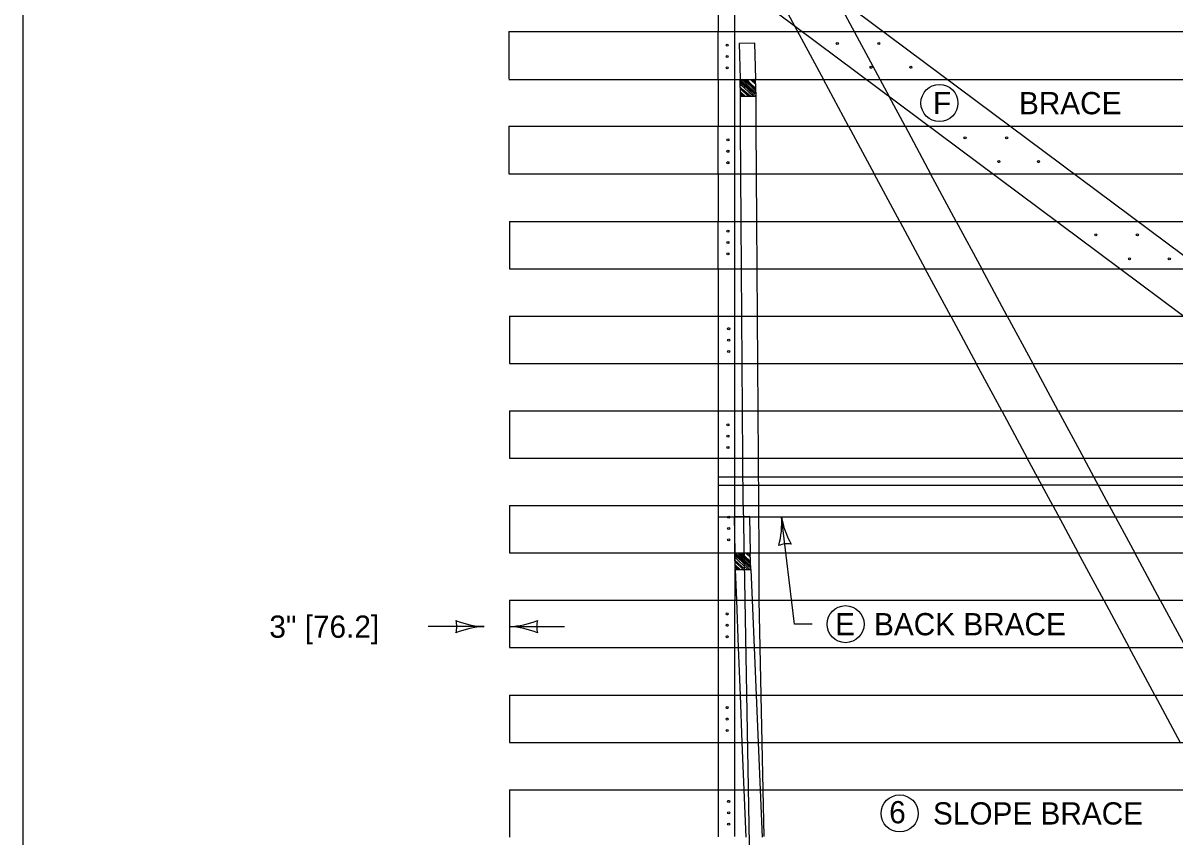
# Model space of a CAD drawing. Extents: x 49991.4 to 50021, y 49987.6 to 50011.4.
# Drawn here: x 49999.384 to 50002.489, y 49994.927 to 49997.122 of the extents above; entities that cross this region are included whole.
import ezdxf

# ---------------------------------------------------------------- set-up
doc = ezdxf.new("R2010")
doc.units = 0
for name, color, linetype in [('Level 1', 7, 'Continuous'), ('Level 2', 7, 'Continuous'), ('Level 3', 7, 'Continuous'), ('Level 4', 7, 'Continuous')]:
    doc.layers.add(name, color=color, linetype=linetype)

msp = doc.modelspace()

# ---------------------------------------------------------------- linework, layer by layer
at = {"layer": 'Level 1'}
for p, q in [((50004.8448, 49994.752), (50001.0146, 49997.6127)), ((50004.7604, 49994.652), (50000.9301, 49997.5128)), ((50001.2572, 49997.2268), (50001.2572, 49997.099)), ((50001.3024, 49997.099), (50001.3024, 49997.2268)), ((50000.6929, 49997.099), (50000.6929, 49996.9713)), ((50000.6929, 49997.099), (50001.4842, 49997.099)), ((50001.7026, 49997.099), (50005.041, 49997.099)), ((50000.6929, 49996.97), (50001.6568, 49996.97)), ((50001.2572, 49996.97), (50001.2572, 49996.8435)), ((50001.3024, 49996.8435), (50001.3024, 49996.97)), ((50001.3176, 49996.9244), (50001.3167, 49996.97)), ((50001.3598, 49996.9244), (50001.3582, 49996.9713)), ((50001.6092, 49996.8435), (50001.5412, 49996.97)), ((50001.8753, 49996.97), (50005.041, 49996.97)), ((50001.3176, 49996.9244), (50001.3598, 49996.9244)), ((50001.3182, 49996.8435), (50001.3176, 49996.9244)), ((50001.3603, 49996.8435), (50001.3598, 49996.9244)), ((50001.7616, 49996.8435), (50001.7182, 49996.9241)), ((50000.6929, 49996.8435), (50000.6929, 49996.7157)), ((50000.6929, 49996.8435), (50001.8262, 49996.8435)), ((50002.0446, 49996.8435), (50005.041, 49996.8435)), ((50000.6929, 49996.7157), (50001.9973, 49996.7157)), ((50001.2572, 49996.7157), (50001.2572, 49996.587)), ((50001.3024, 49996.587), (50001.3024, 49996.7157)), ((50001.3198, 49996.587), (50001.3189, 49996.7157)), ((50001.362, 49996.587), (50001.3611, 49996.7157)), ((50001.7473, 49996.587), (50001.678, 49996.7157)), ((50001.8995, 49996.587), (50001.8304, 49996.7157)), ((50002.2158, 49996.7157), (50005.041, 49996.7157)), ((50000.6947, 49996.587), (50000.6947, 49996.4592)), ((50000.6947, 49996.587), (50001.8995, 49996.587)), ((50001.8995, 49996.587), (50002.1695, 49996.587)), ((50002.3879, 49996.587), (50005.0428, 49996.587)), ((50000.6947, 49996.4592), (50002.3406, 49996.4592)), ((50001.2572, 49996.4592), (50001.2572, 49996.3316)), ((50001.3024, 49996.3316), (50001.3024, 49996.4592)), ((50001.3215, 49996.3316), (50001.3208, 49996.4592)), ((50001.3635, 49996.3316), (50001.3628, 49996.4592)), ((50001.8847, 49996.3316), (50001.8159, 49996.4592)), ((50002.0371, 49996.3316), (50001.9683, 49996.4592)), ((50000.6947, 49996.3316), (50000.6947, 49996.2038)), ((50000.6947, 49996.3316), (50002.5117, 49996.3316)), ((50000.6947, 49996.2038), (50002.6826, 49996.2038)), ((50001.2572, 49996.2038), (50001.2572, 49996.076)), ((50001.3024, 49996.076), (50001.3024, 49996.2038)), ((50001.3232, 49996.076), (50001.3223, 49996.2038)), ((50001.3652, 49996.076), (50001.3643, 49996.2038)), ((50002.0221, 49996.076), (50001.9533, 49996.2038)), ((50002.1745, 49996.076), (50002.1057, 49996.2038)), ((50000.6947, 49996.076), (50000.6947, 49995.9482)), ((50000.6947, 49996.076), (50002.8537, 49996.076)), ((50000.6947, 49995.9482), (50003.0248, 49995.9482)), ((50001.2572, 49995.9482), (50001.2572, 49995.8204)), ((50001.3024, 49995.8204), (50001.3024, 49995.9482)), ((50001.3249, 49995.8204), (50001.324, 49995.9482)), ((50001.3669, 49995.8204), (50001.366, 49995.9482)), ((50002.1595, 49995.8204), (50002.0909, 49995.9482)), ((50002.3119, 49995.8204), (50002.2432, 49995.9482)), ((50001.3024, 49995.898), (50001.3244, 49995.898)), ((50001.3024, 49995.8757), (50001.3245, 49995.8757)), ((50001.3664, 49995.898), (50002.1178, 49995.898)), ((50001.3665, 49995.8757), (50002.1298, 49995.8757)), ((50002.2702, 49995.898), (50002.8073, 49995.898)), ((50002.2822, 49995.8757), (50002.8072, 49995.8757)), ((50000.6947, 49995.8204), (50000.6947, 49995.6928)), ((50000.6947, 49995.8204), (50003.1959, 49995.8204)), ((50000.6947, 49995.6928), (50003.367, 49995.6928)), ((50001.2572, 49995.6936), (50001.2572, 49995.565)), ((50001.3033, 49995.6483), (50001.3024, 49995.6939)), ((50001.3024, 49995.6927), (50001.3024, 49995.565)), ((50001.3455, 49995.6483), (50001.3441, 49995.693)), ((50001.3685, 49995.565), (50001.3677, 49995.6928)), ((50002.2971, 49995.565), (50002.2283, 49995.6928)), ((50002.4493, 49995.565), (50002.3806, 49995.6928)), ((50001.3033, 49995.6483), (50001.3455, 49995.6483)), ((50001.3033, 49995.6483), (50001.3067, 49995.565)), ((50001.3455, 49995.6483), (50001.349, 49995.565)), ((50000.6947, 49995.565), (50000.6947, 49995.4372)), ((50000.6947, 49995.565), (50003.5379, 49995.565)), ((50000.6947, 49995.4372), (50003.709, 49995.4372)), ((50001.2572, 49995.4372), (50001.2572, 49995.3094)), ((50001.3024, 49995.3094), (50001.3024, 49995.4372)), ((50001.3118, 49995.4372), (50001.3167, 49995.3094)), ((50001.3543, 49995.4372), (50001.3596, 49995.3094)), ((50001.3735, 49995.3094), (50001.3711, 49995.4372)), ((50002.4345, 49995.3094), (50002.3657, 49995.4372)), ((50000.6947, 49995.3094), (50003.8801, 49995.3094)), ((50000.6947, 49995.3094), (50000.6947, 49995.1816)), ((50000.6947, 49995.1816), (50004.0512, 49995.1816)), ((50001.2572, 49995.1816), (50001.2572, 49995.054)), ((50001.3024, 49995.054), (50001.3024, 49995.1816)), ((50001.3218, 49995.1816), (50001.3269, 49995.054)), ((50001.3651, 49995.1816), (50001.3704, 49995.054)), ((50001.3787, 49995.054), (50001.3763, 49995.1816)), ((50000.6947, 49995.054), (50000.6947, 49994.9262)), ((50000.6947, 49995.054), (50004.2222, 49995.054))]:
    msp.add_line(p, q, dxfattribs=at)
msp.add_lwpolyline([(49999.3835, 49998.9992), (50016.7501, 49998.9992), (50016.7501, 49987.7988), (49999.3835, 49987.7988)], close=True, dxfattribs=at)
for points in [[(50001.3167, 49996.9657), (50001.317, 49996.9655), (50001.3293, 49996.9553), (50001.3416, 49996.9443), (50001.3568, 49996.9302)], [(50001.3597, 49996.93), (50001.3429, 49996.9454), (50001.3306, 49996.9565), (50001.3205, 49996.9662), (50001.3171, 49996.9699)], [(50001.3594, 49996.9327), (50001.3516, 49996.9401), (50001.3406, 49996.9509), (50001.3265, 49996.9653), (50001.3216, 49996.9699)], [(50001.3594, 49996.9379), (50001.3453, 49996.9516), (50001.3269, 49996.9692), (50001.3263, 49996.9698)], [(50001.3594, 49996.9408), (50001.3513, 49996.9492), (50001.3298, 49996.97)], [(50001.3592, 49996.9453), (50001.3522, 49996.9521), (50001.34, 49996.9633), (50001.3333, 49996.97)], [(50001.3588, 49996.9565), (50001.3576, 49996.9577), (50001.3481, 49996.966), (50001.3444, 49996.9699)], [(50001.3585, 49996.9607), (50001.3577, 49996.9614), (50001.3483, 49996.9701)], [(50001.3584, 49996.9637), (50001.3533, 49996.9685), (50001.352, 49996.97)], [(50001.354, 49996.9276), (50001.3366, 49996.9447), (50001.3279, 49996.9531), (50001.3226, 49996.9566), (50001.3188, 49996.9588), (50001.3169, 49996.9607)], [(50001.354, 49996.9276), (50001.3366, 49996.9447), (50001.3279, 49996.9531), (50001.3226, 49996.9566), (50001.3188, 49996.9588), (50001.3169, 49996.9607)], [(50001.352, 49996.9246), (50001.3287, 49996.9461), (50001.3223, 49996.9517), (50001.317, 49996.9557)], [(50001.3443, 49996.9244), (50001.3244, 49996.9422), (50001.3171, 49996.9492)], [(50001.339, 49996.9244), (50001.3172, 49996.9444), (50001.3172, 49996.9444)], [(50001.3308, 49996.9244), (50001.3186, 49996.9357), (50001.3174, 49996.937)], [(50001.3278, 49996.9244), (50001.3228, 49996.9288), (50001.3174, 49996.9338)], [(50001.3235, 49996.9244), (50001.3228, 49996.925), (50001.3175, 49996.9297)], [(50001.3578, 49996.9244), (50001.3557, 49996.9262)], [(50001.3583, 49996.9288), (50001.3596, 49996.9276)], [(50001.3453, 49995.6518), (50001.3274, 49995.6682), (50001.3152, 49995.6792), (50001.3028, 49995.6894), (50001.3026, 49995.6896)], [(50001.3454, 49995.6539), (50001.3287, 49995.6695), (50001.3165, 49995.6804), (50001.3063, 49995.6902), (50001.3037, 49995.6928)], [(50001.3452, 49995.6566), (50001.3374, 49995.664), (50001.3265, 49995.6748), (50001.3123, 49995.6893), (50001.3084, 49995.6929)], [(50001.345, 49995.662), (50001.3312, 49995.6755), (50001.3128, 49995.693)], [(50001.3451, 49995.6649), (50001.3371, 49995.6733), (50001.3163, 49995.6931)], [(50001.3449, 49995.6693), (50001.3379, 49995.676), (50001.3258, 49995.6872), (50001.3204, 49995.6925)], [(50001.3444, 49995.6806), (50001.3434, 49995.6816), (50001.3339, 49995.6899), (50001.3311, 49995.6928)], [(50001.3444, 49995.6845), (50001.3434, 49995.6854), (50001.3354, 49995.6928)], [(50001.3443, 49995.6875), (50001.3391, 49995.6924), (50001.3386, 49995.693)], [(50001.3432, 49995.6484), (50001.3223, 49995.6686), (50001.3137, 49995.677), (50001.3084, 49995.6806), (50001.3046, 49995.6828), (50001.3027, 49995.6846)], [(50001.3378, 49995.6484), (50001.3145, 49995.67), (50001.308, 49995.6756), (50001.3028, 49995.6796)], [(50001.33, 49995.6483), (50001.3102, 49995.6661), (50001.3028, 49995.6731)], [(50001.3247, 49995.6483), (50001.3031, 49995.6683), (50001.3031, 49995.6683)], [(50001.3166, 49995.6483), (50001.3044, 49995.6596), (50001.3031, 49995.6609)], [(50001.3136, 49995.6483), (50001.3087, 49995.6527), (50001.3032, 49995.6578)], [(50001.3093, 49995.6483), (50001.3085, 49995.649), (50001.3033, 49995.6536)]]:
    msp.add_lwpolyline(points, dxfattribs=at)
for centre in [(50001.2819, 49997.0623), (50001.5787, 49997.0672), (50001.6909, 49997.0672), (50001.2819, 49997.0316), (50001.2819, 49997.001), (50001.6698, 49997.0027), (50001.7769, 49997.0027), (50001.2839, 49996.8068), (50001.9231, 49996.8127), (50002.0353, 49996.8127), (50001.2839, 49996.7761), (50001.2839, 49996.7454), (50002.0143, 49996.7482), (50002.1213, 49996.7482), (50001.2839, 49996.5606), (50001.2839, 49996.5299), (50002.2756, 49996.5507), (50002.3878, 49996.5507), (50001.2839, 49996.4992), (50002.3667, 49996.4862), (50002.4738, 49996.4862), (50001.2859, 49996.2976), (50001.2859, 49996.2669), (50001.2859, 49996.2362), (50001.2839, 49996.0383), (50001.2839, 49996.0076), (50001.2839, 49995.977), (50001.2859, 49995.7892), (50001.2859, 49995.7586), (50001.2859, 49995.7279), (50001.2819, 49995.5281), (50001.2819, 49995.4975), (50001.2819, 49995.4668), (50001.2819, 49995.2754), (50001.2819, 49995.2447), (50001.2819, 49995.2141), (50001.2859, 49995.0226), (50001.2859, 49994.992), (50001.2859, 49994.9613)]:
    msp.add_ellipse(centre, major_axis=(0.00285, 0), ratio=0.940299, dxfattribs=at)
at = {"layer": 'Level 2'}
for centre in [(50001.8541, 49996.9064), (50001.601, 49995.5006), (50001.7468, 49994.9901)]:
    msp.add_circle(centre, 0.05, dxfattribs=at)
at = {"layer": 'Level 3'}
for p, q in [((50001.4635, 49995.5006), (50001.4283, 49995.7899)), ((50000.6266, 49995.4939), (50000.4761, 49995.4939)), ((50000.6947, 49995.4939), (50000.8437, 49995.4939)), ((50001.511, 49995.5006), (50001.4635, 49995.5006))]:
    msp.add_line(p, q, dxfattribs=at)
for centre, radius, start, end in [((50001.2067, 49995.7722), 0.2223, 344.389, 4.5726), ((50001.6579, 49995.8294), 0.233, 189.7603, 209.0102), ((50001.4438, 49995.6626), 0.0548, 79.0719, 114.7942), ((50000.6358, 49995.716), 0.2223, 247.456, 267.6395), ((50000.4984, 49995.4939), 0.0548, 342.1388, 17.8612), ((50000.6832, 49995.7266), 0.233, 272.8273, 292.0772), ((50000.8229, 49995.4939), 0.0548, 162.1388, 197.8612), ((50000.6381, 49995.2612), 0.233, 92.8273, 112.0772), ((50000.6855, 49995.2718), 0.2223, 67.456, 87.6395)]:
    msp.add_arc(centre, radius, start, end, dxfattribs=at)
at = {"layer": 'Level 4'}
for p, q in [((50001.3169, 49997.3871), (50001.5412, 49996.97)), ((50001.5715, 49997.1969), (50001.7182, 49996.9241)), ((50001.2572, 49996.97), (50001.2572, 49997.099)), ((50001.3024, 49996.97), (50001.3024, 49997.099)), ((50001.4842, 49997.099), (50001.7026, 49997.099)), ((50001.3566, 49997.0674), (50001.3146, 49997.0666)), ((50001.3146, 49997.0666), (50001.3166, 49996.9713)), ((50001.3587, 49996.9713), (50001.3566, 49997.0674)), ((50001.6568, 49996.97), (50001.8753, 49996.97)), ((50001.2572, 49996.7157), (50001.2572, 49996.8435)), ((50001.3024, 49996.7157), (50001.3024, 49996.8435)), ((50001.3189, 49996.7157), (50001.3182, 49996.8435)), ((50001.3611, 49996.7157), (50001.3603, 49996.8435)), ((50001.6092, 49996.8435), (50001.678, 49996.7157)), ((50001.7616, 49996.8435), (50001.8304, 49996.7157)), ((50001.8262, 49996.8435), (50002.0446, 49996.8435)), ((50001.9973, 49996.7157), (50002.2158, 49996.7157)), ((50001.2572, 49996.4592), (50001.2572, 49996.587)), ((50001.3024, 49996.4592), (50001.3024, 49996.587)), ((50001.3208, 49996.4592), (50001.3198, 49996.587)), ((50001.3628, 49996.4592), (50001.362, 49996.587)), ((50001.7473, 49996.587), (50001.8159, 49996.4592)), ((50001.8995, 49996.587), (50001.9683, 49996.4592)), ((50002.1695, 49996.587), (50002.3879, 49996.587)), ((50002.3406, 49996.4592), (50002.559, 49996.4592)), ((50001.2572, 49996.3316), (50001.2572, 49996.2038)), ((50001.3024, 49996.2038), (50001.3024, 49996.3316)), ((50001.3223, 49996.2038), (50001.3215, 49996.3316)), ((50001.3644, 49996.2038), (50001.3635, 49996.3316)), ((50001.8847, 49996.3316), (50001.9533, 49996.2038)), ((50002.0371, 49996.3316), (50002.1057, 49996.2038)), ((50001.2572, 49996.0751), (50001.2572, 49995.9482)), ((50001.3024, 49995.9482), (50001.3024, 49996.076)), ((50001.324, 49995.9482), (50001.3232, 49996.076)), ((50001.3661, 49995.9482), (50001.3652, 49996.076)), ((50002.0221, 49996.076), (50002.0909, 49995.9482)), ((50002.1745, 49996.076), (50002.2432, 49995.9482)), ((50001.2572, 49995.898), (50001.3024, 49995.898)), ((50001.2572, 49995.8757), (50001.3024, 49995.8757)), ((50001.3244, 49995.898), (50001.3664, 49995.898)), ((50001.3245, 49995.8757), (50001.3665, 49995.8757)), ((50002.1178, 49995.898), (50002.2702, 49995.898)), ((50002.2822, 49995.8757), (50002.1298, 49995.8757)), ((50001.2572, 49995.8194), (50001.2572, 49995.6936)), ((50001.3024, 49995.693), (50001.3024, 49995.8187)), ((50001.3249, 49995.8204), (50001.3455, 49994.6706)), ((50001.3677, 49995.6928), (50001.3669, 49995.8204)), ((50002.1595, 49995.8204), (50002.2283, 49995.6928)), ((50002.3119, 49995.8204), (50002.3806, 49995.6928)), ((50001.2572, 49995.7899), (50004.4313, 49995.7899)), ((50001.3425, 49995.7913), (50001.3005, 49995.7905)), ((50001.3005, 49995.7905), (50001.3024, 49995.6952)), ((50001.3446, 49995.6932), (50001.3425, 49995.7913)), ((50001.2572, 49995.565), (50001.2572, 49995.4393)), ((50001.3024, 49995.4382), (50001.3024, 49995.565)), ((50001.3067, 49995.565), (50001.3118, 49995.4372)), ((50001.349, 49995.565), (50001.3543, 49995.4372)), ((50001.3711, 49995.4382), (50001.3685, 49995.565)), ((50002.2971, 49995.565), (50002.3657, 49995.4372)), ((50002.4493, 49995.565), (50002.5181, 49995.4372)), ((50001.2572, 49995.3085), (50001.2572, 49995.1816)), ((50001.3024, 49995.1816), (50001.3024, 49995.3074)), ((50001.3167, 49995.3094), (50001.3218, 49995.1816)), ((50001.3596, 49995.3094), (50001.3651, 49995.1816)), ((50001.376, 49995.1816), (50001.3735, 49995.3085)), ((50002.4345, 49995.3094), (50002.5032, 49995.1816)), ((50001.2572, 49995.054), (50001.2572, 49994.9269)), ((50001.3024, 49994.9276), (50001.3024, 49995.054)), ((50001.3269, 49995.054), (50001.3318, 49994.9262)), ((50001.3704, 49995.054), (50001.3758, 49994.9262)), ((50001.3812, 49994.9276), (50001.3787, 49995.054))]:
    msp.add_line(p, q, dxfattribs=at)

# ---------------------------------------------------------------- texts
at = {"layer": 'Level 2'}
for s, p in [('F', (50001.8369, 49996.8765)), ('BRACE', (50002.0685, 49996.876)), ('3" [76.2]', (50000.0475, 49995.4639)), ('E', (50001.573, 49995.4706)), ('BACK BRACE', (50001.6778, 49995.4706)), ('6', (50001.7187, 49994.9634)), ('SLOPE BRACE', (50001.8368, 49994.9601))]:
    msp.add_text(s, height=0.06, dxfattribs=at).set_placement(p)

doc.saveas('drawing.dxf')
